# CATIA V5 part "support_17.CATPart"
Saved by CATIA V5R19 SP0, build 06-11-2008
Part number: support_17
Bounding box of the stored display mesh (mm): x -50 to 50, y -23.187 to 127.024, z -126.581 to 111.476
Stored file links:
  C:\Users\Thinkmotion2\Desktop\Pack 2\CFAO_2010\abaussand\CFAO_abaussand_Catia_V5R20\support_17.CATPart
  C:\Users\Thinkmotion2\Desktop\Pack 2\CFAO_2010\abaussand\CFAO_abaussand_Catia_V5R20\Axe_11.CATPart
  C:\Users\Thinkmotion2\Desktop\Pack 2\CFAO_2010\abaussand\CFAO_abaussand_Catia_V5R20\abaussand.CATProduct
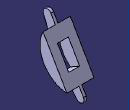
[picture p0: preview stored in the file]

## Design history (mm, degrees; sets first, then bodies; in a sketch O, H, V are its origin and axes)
Body1 (main body)
  Sketch1 on yz-plane, origin (0, 0, 0), H (0, 1, 0), V (0, 0, 1)
    line L1 (5, 103.923) -> (65, 0)
    point P2 (65, 0)
    line L2 (0, 30) -> (-22.2764, 91.2039)
    point P3 (0, 30)
    arc A1 centre (-8.0818, 96.3703) radius 15.1056 from (5, 103.923) to (-22.2764, 91.2039) ccw
    reference projected line E1 through (0, 0) direction (-1, 0)
    line L3 (0, 30) -> (25.173, 0)
    point P6 (25.173, 0)
    line L4 (25.173, 0) -> (65, 0)
    angle L1 H = 60
    length L1 = 120
    distance P2 V = 65
    angle L2 H = 70
    distance P3 E1 = 30
    angle L3 H = 50
    tangency: A1 L2, A1 L1
    coincidence: P6 H, P3 V
    horizontal: L4 H
  Pad1: profile Sketch1, direction (1, 0, 0), length 5, mirrored extent
  Plane1: type Angle, RefPlane zx-plane, Direction edge [face of Pad1 from Sketch1.L1 | face of Pad1 from Sketch1.L4], Angle 120
  Sketch2 on yz-plane, origin (0, 0, 0), H (0, 1, 0), V (0, 0, 1)
    line L1 (21.25, 75.7772) -> (108.75, -75.7772)
    point P2 (108.75, -75.7772)
    arc A1 centre (115.2649, 29.0205) radius 105 from (21.25, 75.7772) to (108.75, -75.7772) ccw
    reference projected line E1 (65, 0) -> (5, 103.923) from edge [face of Pad1 from Sketch1.L1 | end face of Pad1]
    length L1 = 175
    distance P2 H = 75.7772
    radius A1 = 105
    coincidence: L1 E1
  Mirror1: of Pad1, about Plane1
  Pad2: profile Sketch2, direction (1, 0, 0), length 50, mirrored extent
  Sketch3 on face of Pad2, origin (0, 48.75, 28.1458), H (-1, 0, 0), V (0, -0.5, 0.866)
    line L1 (-20, 9) -> (20, 9)
    line L2 (20, 9) -> (20, -74)
    line L3 (20, -74) -> (-20, -74)
    line L4 (-20, -74) -> (-20, 9)
    reference projected line E1 (50, 55) -> (5, 55) from edge [face of Pad2 from Sketch2.A1 | face of Pad2]
    reference projected line E2 (50, -120) -> (5, -120) from edge [face of Pad2 | face of Pad2 from Sketch2.A1]
    length L1 = 40
    distance L4 V = 20
    distance L1 E1 = 46
    distance L3 E2 = 46
    horizontal: L1 H, L3 H
    vertical: L2 V, L4 V
  Pocket1: profile Sketch3, direction (0, -0.866, -0.5), through (limit type 3)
